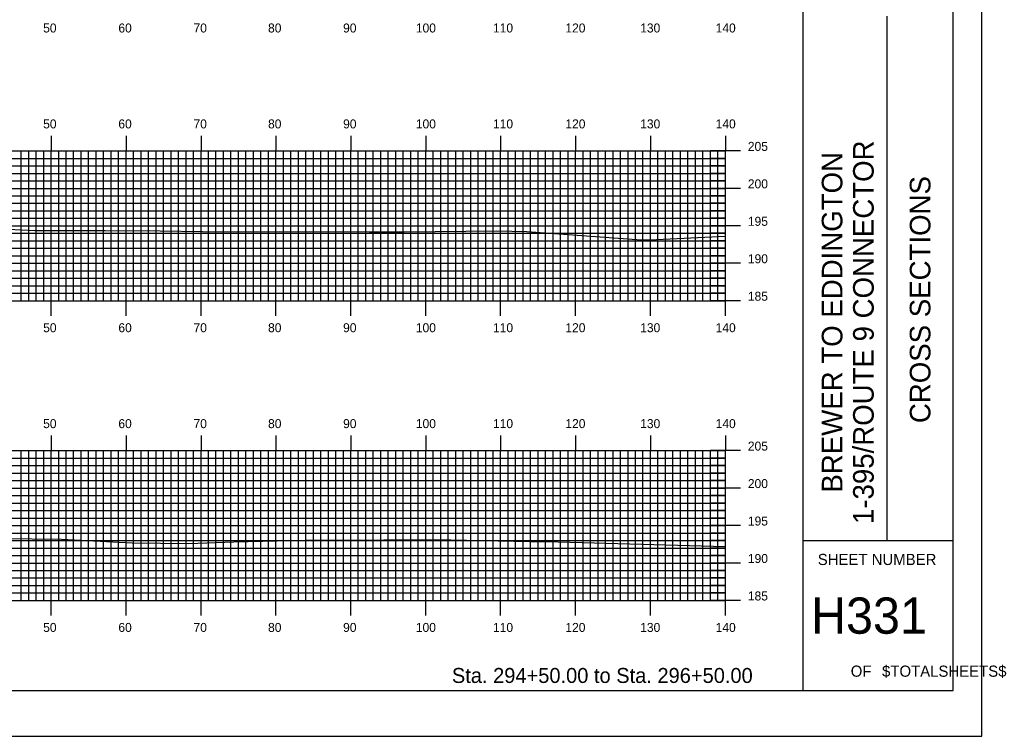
# Model space of a CAD drawing. Extents: x 1814522 to 1814865, y 442591 to 442811.
# Drawn here: x 1814733.3 to 1814865, y 442590.5 to 442686.2 of the extents above; entities that cross this region are included whole.
import ezdxf

# ---------------------------------------------------------------- set-up
doc = ezdxf.new("R2010")
doc.units = 0
for name, color, linetype in [('BORDER', 7, 'Continuous'), ('H_V ANNOTATION', 7, 'Continuous'), ('MAJOR', 7, 'Continuous'), ('MINOR', 7, 'Continuous'), ('PLOT BOUNDARY', 7, 'Continuous'), ('S_Roadway_Centerline', 7, 'Continuous')]:
    doc.layers.add(name, color=color, linetype=linetype)

msp = doc.modelspace()

# ---------------------------------------------------------------- linework, layer by layer
at = {"layer": 'BORDER'}
for p, q in [((1814837.91, 442596.67), (1814837.91, 442806.67)), ((1814849.09, 442616.67), (1814849.09, 442686.67)), ((1814837.91, 442616.67), (1814857.91, 442616.67))]:
    msp.add_line(p, q, dxfattribs=at)
msp.add_lwpolyline([(1814537.91, 442596.67), (1814857.91, 442596.67), (1814857.91, 442806.67), (1814537.91, 442806.67)], close=True, dxfattribs=at)
at = {"layer": 'MAJOR'}
for p, q in [((1814737.51, 442670.67), (1814737.51, 442668.67)), ((1814747.51, 442670.67), (1814747.51, 442668.67)), ((1814757.51, 442670.67), (1814757.51, 442668.67)), ((1814767.51, 442670.67), (1814767.51, 442668.67)), ((1814777.51, 442670.67), (1814777.51, 442668.67)), ((1814787.51, 442670.67), (1814787.51, 442668.67)), ((1814797.51, 442670.67), (1814797.51, 442668.67)), ((1814807.51, 442670.67), (1814807.51, 442668.67)), ((1814817.51, 442670.67), (1814817.51, 442668.67)), ((1814827.51, 442670.67), (1814827.51, 442668.67)), ((1814547.51, 442668.67), (1814827.51, 442668.67)), ((1814547.51, 442668.67), (1814827.51, 442668.67)), ((1814737.51, 442648.67), (1814737.51, 442668.67)), ((1814747.51, 442648.67), (1814747.51, 442668.67)), ((1814757.51, 442648.67), (1814757.51, 442668.67)), ((1814767.51, 442648.67), (1814767.51, 442668.67)), ((1814777.51, 442648.67), (1814777.51, 442668.67)), ((1814787.51, 442648.67), (1814787.51, 442668.67)), ((1814797.51, 442648.67), (1814797.51, 442668.67)), ((1814807.51, 442648.67), (1814807.51, 442668.67)), ((1814817.51, 442648.67), (1814817.51, 442668.67)), ((1814829.51, 442668.67), (1814825.5, 442668.67)), ((1814827.51, 442648.67), (1814827.51, 442668.67)), ((1814827.51, 442648.67), (1814827.51, 442668.67)), ((1814547.51, 442663.67), (1814827.51, 442663.67)), ((1814829.51, 442663.67), (1814825.5, 442663.67)), ((1814547.51, 442658.67), (1814827.51, 442658.67)), ((1814829.51, 442658.67), (1814825.5, 442658.67)), ((1814547.51, 442653.67), (1814827.51, 442653.67)), ((1814829.51, 442653.67), (1814825.5, 442653.67)), ((1814547.51, 442648.67), (1814827.51, 442648.67)), ((1814547.51, 442648.67), (1814827.51, 442648.67)), ((1814737.51, 442646.66), (1814737.51, 442648.67)), ((1814747.51, 442646.66), (1814747.51, 442648.67)), ((1814757.51, 442646.66), (1814757.51, 442648.67)), ((1814767.51, 442646.66), (1814767.51, 442648.67)), ((1814777.51, 442646.66), (1814777.51, 442648.67)), ((1814787.51, 442646.66), (1814787.51, 442648.67)), ((1814797.51, 442646.66), (1814797.51, 442648.67)), ((1814807.51, 442646.66), (1814807.51, 442648.67)), ((1814817.51, 442646.66), (1814817.51, 442648.67)), ((1814829.51, 442648.67), (1814825.5, 442648.67)), ((1814827.51, 442646.66), (1814827.51, 442648.67)), ((1814737.51, 442630.67), (1814737.51, 442628.67)), ((1814747.51, 442630.67), (1814747.51, 442628.67)), ((1814757.51, 442630.67), (1814757.51, 442628.67)), ((1814767.51, 442630.67), (1814767.51, 442628.67)), ((1814777.51, 442630.67), (1814777.51, 442628.67)), ((1814787.51, 442630.67), (1814787.51, 442628.67)), ((1814797.51, 442630.67), (1814797.51, 442628.67)), ((1814807.51, 442630.67), (1814807.51, 442628.67)), ((1814817.51, 442630.67), (1814817.51, 442628.67)), ((1814827.51, 442630.67), (1814827.51, 442628.67)), ((1814547.51, 442628.67), (1814827.51, 442628.67)), ((1814547.51, 442628.67), (1814827.51, 442628.67)), ((1814737.51, 442608.67), (1814737.51, 442628.67)), ((1814747.51, 442608.67), (1814747.51, 442628.67)), ((1814757.51, 442608.67), (1814757.51, 442628.67)), ((1814767.51, 442608.67), (1814767.51, 442628.67)), ((1814777.51, 442608.67), (1814777.51, 442628.67)), ((1814787.51, 442608.67), (1814787.51, 442628.67)), ((1814797.51, 442608.67), (1814797.51, 442628.67)), ((1814807.51, 442608.67), (1814807.51, 442628.67)), ((1814817.51, 442608.67), (1814817.51, 442628.67)), ((1814829.51, 442628.67), (1814825.5, 442628.67)), ((1814827.51, 442608.67), (1814827.51, 442628.67)), ((1814827.51, 442608.67), (1814827.51, 442628.67)), ((1814547.51, 442623.67), (1814827.51, 442623.67)), ((1814829.51, 442623.67), (1814825.5, 442623.67)), ((1814547.51, 442618.67), (1814827.51, 442618.67)), ((1814829.51, 442618.67), (1814825.5, 442618.67)), ((1814547.51, 442613.67), (1814827.51, 442613.67)), ((1814829.51, 442613.67), (1814825.5, 442613.67)), ((1814547.51, 442608.67), (1814827.51, 442608.67)), ((1814547.51, 442608.67), (1814827.51, 442608.67)), ((1814737.51, 442606.66), (1814737.51, 442608.67)), ((1814747.51, 442606.66), (1814747.51, 442608.67)), ((1814757.51, 442606.66), (1814757.51, 442608.67)), ((1814767.51, 442606.66), (1814767.51, 442608.67)), ((1814777.51, 442606.66), (1814777.51, 442608.67)), ((1814787.51, 442606.66), (1814787.51, 442608.67)), ((1814797.51, 442606.66), (1814797.51, 442608.67)), ((1814807.51, 442606.66), (1814807.51, 442608.67)), ((1814817.51, 442606.66), (1814817.51, 442608.67)), ((1814829.51, 442608.67), (1814825.5, 442608.67)), ((1814827.51, 442606.66), (1814827.51, 442608.67))]:
    msp.add_line(p, q, dxfattribs=at)
at = {"layer": 'MINOR'}
for p, q in [((1814733.51, 442648.67), (1814733.51, 442668.67)), ((1814734.51, 442648.67), (1814734.51, 442668.67)), ((1814735.51, 442648.67), (1814735.51, 442668.67)), ((1814736.51, 442648.67), (1814736.51, 442668.67)), ((1814738.51, 442648.67), (1814738.51, 442668.67)), ((1814739.51, 442648.67), (1814739.51, 442668.67)), ((1814740.51, 442648.67), (1814740.51, 442668.67)), ((1814741.51, 442648.67), (1814741.51, 442668.67)), ((1814742.51, 442648.67), (1814742.51, 442668.67)), ((1814743.51, 442648.67), (1814743.51, 442668.67)), ((1814744.51, 442648.67), (1814744.51, 442668.67)), ((1814745.51, 442648.67), (1814745.51, 442668.67)), ((1814746.51, 442648.67), (1814746.51, 442668.67)), ((1814748.51, 442648.67), (1814748.51, 442668.67)), ((1814749.51, 442648.67), (1814749.51, 442668.67)), ((1814750.51, 442648.67), (1814750.51, 442668.67)), ((1814751.51, 442648.67), (1814751.51, 442668.67)), ((1814752.51, 442648.67), (1814752.51, 442668.67)), ((1814753.51, 442648.67), (1814753.51, 442668.67)), ((1814754.51, 442648.67), (1814754.51, 442668.67)), ((1814755.51, 442648.67), (1814755.51, 442668.67)), ((1814756.51, 442648.67), (1814756.51, 442668.67)), ((1814758.51, 442648.67), (1814758.51, 442668.67)), ((1814759.51, 442648.67), (1814759.51, 442668.67)), ((1814760.51, 442648.67), (1814760.51, 442668.67)), ((1814761.51, 442648.67), (1814761.51, 442668.67)), ((1814762.51, 442648.67), (1814762.51, 442668.67)), ((1814763.51, 442648.67), (1814763.51, 442668.67)), ((1814764.51, 442648.67), (1814764.51, 442668.67)), ((1814765.51, 442648.67), (1814765.51, 442668.67)), ((1814766.51, 442648.67), (1814766.51, 442668.67)), ((1814768.51, 442648.67), (1814768.51, 442668.67)), ((1814769.51, 442648.67), (1814769.51, 442668.67)), ((1814770.51, 442648.67), (1814770.51, 442668.67)), ((1814771.51, 442648.67), (1814771.51, 442668.67)), ((1814772.51, 442648.67), (1814772.51, 442668.67)), ((1814773.51, 442648.67), (1814773.51, 442668.67)), ((1814774.51, 442648.67), (1814774.51, 442668.67)), ((1814775.51, 442648.67), (1814775.51, 442668.67)), ((1814776.51, 442648.67), (1814776.51, 442668.67)), ((1814778.51, 442648.67), (1814778.51, 442668.67)), ((1814779.51, 442648.67), (1814779.51, 442668.67)), ((1814780.51, 442648.67), (1814780.51, 442668.67)), ((1814781.51, 442648.67), (1814781.51, 442668.67)), ((1814782.51, 442648.67), (1814782.51, 442668.67)), ((1814783.51, 442648.67), (1814783.51, 442668.67)), ((1814784.51, 442648.67), (1814784.51, 442668.67)), ((1814785.51, 442648.67), (1814785.51, 442668.67)), ((1814786.51, 442648.67), (1814786.51, 442668.67)), ((1814788.51, 442648.67), (1814788.51, 442668.67)), ((1814789.51, 442648.67), (1814789.51, 442668.67)), ((1814790.51, 442648.67), (1814790.51, 442668.67)), ((1814791.51, 442648.67), (1814791.51, 442668.67)), ((1814792.51, 442648.67), (1814792.51, 442668.67)), ((1814793.51, 442648.67), (1814793.51, 442668.67)), ((1814794.51, 442648.67), (1814794.51, 442668.67)), ((1814795.51, 442648.67), (1814795.51, 442668.67)), ((1814796.51, 442648.67), (1814796.51, 442668.67)), ((1814798.51, 442648.67), (1814798.51, 442668.67)), ((1814799.51, 442648.67), (1814799.51, 442668.67)), ((1814800.51, 442648.67), (1814800.51, 442668.67)), ((1814801.51, 442648.67), (1814801.51, 442668.67)), ((1814802.51, 442648.67), (1814802.51, 442668.67)), ((1814803.51, 442648.67), (1814803.51, 442668.67)), ((1814804.51, 442648.67), (1814804.51, 442668.67)), ((1814805.51, 442648.67), (1814805.51, 442668.67)), ((1814806.51, 442648.67), (1814806.51, 442668.67)), ((1814808.51, 442648.67), (1814808.51, 442668.67)), ((1814809.51, 442648.67), (1814809.51, 442668.67)), ((1814810.51, 442648.67), (1814810.51, 442668.67)), ((1814811.51, 442648.67), (1814811.51, 442668.67)), ((1814812.51, 442648.67), (1814812.51, 442668.67)), ((1814813.51, 442648.67), (1814813.51, 442668.67)), ((1814814.51, 442648.67), (1814814.51, 442668.67)), ((1814815.51, 442648.67), (1814815.51, 442668.67)), ((1814816.51, 442648.67), (1814816.51, 442668.67)), ((1814818.51, 442648.67), (1814818.51, 442668.67)), ((1814819.51, 442648.67), (1814819.51, 442668.67)), ((1814820.51, 442648.67), (1814820.51, 442668.67)), ((1814821.51, 442648.67), (1814821.51, 442668.67)), ((1814822.51, 442648.67), (1814822.51, 442668.67)), ((1814823.51, 442648.67), (1814823.51, 442668.67)), ((1814824.51, 442648.67), (1814824.51, 442668.67)), ((1814825.51, 442648.67), (1814825.51, 442668.67)), ((1814826.51, 442648.67), (1814826.51, 442668.67)), ((1814547.51, 442667.67), (1814827.51, 442667.67)), ((1814547.51, 442666.67), (1814827.51, 442666.67)), ((1814827.51, 442667.67), (1814825.5, 442667.67)), ((1814827.51, 442666.67), (1814825.5, 442666.67)), ((1814547.51, 442665.67), (1814827.51, 442665.67)), ((1814827.51, 442665.67), (1814825.5, 442665.67)), ((1814547.51, 442664.67), (1814827.51, 442664.67)), ((1814827.51, 442664.67), (1814825.5, 442664.67)), ((1814547.51, 442662.67), (1814827.51, 442662.67)), ((1814827.51, 442662.67), (1814825.5, 442662.67)), ((1814547.51, 442661.67), (1814827.51, 442661.67)), ((1814827.51, 442661.67), (1814825.5, 442661.67)), ((1814547.51, 442660.67), (1814827.51, 442660.67)), ((1814827.51, 442660.67), (1814825.5, 442660.67)), ((1814547.51, 442659.67), (1814827.51, 442659.67)), ((1814827.51, 442659.67), (1814825.5, 442659.67)), ((1814547.51, 442657.67), (1814827.51, 442657.67)), ((1814827.51, 442657.67), (1814825.5, 442657.67)), ((1814547.51, 442656.67), (1814827.51, 442656.67)), ((1814827.51, 442656.67), (1814825.5, 442656.67)), ((1814547.51, 442655.67), (1814827.51, 442655.67)), ((1814547.51, 442654.67), (1814827.51, 442654.67)), ((1814827.51, 442655.67), (1814825.5, 442655.67)), ((1814827.51, 442654.67), (1814825.5, 442654.67)), ((1814547.51, 442652.67), (1814827.51, 442652.67)), ((1814827.51, 442652.67), (1814825.5, 442652.67)), ((1814547.51, 442651.67), (1814827.51, 442651.67)), ((1814547.51, 442650.67), (1814827.51, 442650.67)), ((1814827.51, 442651.67), (1814825.5, 442651.67)), ((1814827.51, 442650.67), (1814825.5, 442650.67)), ((1814547.51, 442649.67), (1814827.51, 442649.67)), ((1814827.51, 442649.67), (1814825.5, 442649.67)), ((1814733.51, 442608.67), (1814733.51, 442628.67)), ((1814734.51, 442608.67), (1814734.51, 442628.67)), ((1814735.51, 442608.67), (1814735.51, 442628.67)), ((1814736.51, 442608.67), (1814736.51, 442628.67)), ((1814738.51, 442608.67), (1814738.51, 442628.67)), ((1814739.51, 442608.67), (1814739.51, 442628.67)), ((1814740.51, 442608.67), (1814740.51, 442628.67)), ((1814741.51, 442608.67), (1814741.51, 442628.67)), ((1814742.51, 442608.67), (1814742.51, 442628.67)), ((1814743.51, 442608.67), (1814743.51, 442628.67)), ((1814744.51, 442608.67), (1814744.51, 442628.67)), ((1814745.51, 442608.67), (1814745.51, 442628.67)), ((1814746.51, 442608.67), (1814746.51, 442628.67)), ((1814748.51, 442608.67), (1814748.51, 442628.67)), ((1814749.51, 442608.67), (1814749.51, 442628.67)), ((1814750.51, 442608.67), (1814750.51, 442628.67)), ((1814751.51, 442608.67), (1814751.51, 442628.67)), ((1814752.51, 442608.67), (1814752.51, 442628.67)), ((1814753.51, 442608.67), (1814753.51, 442628.67)), ((1814754.51, 442608.67), (1814754.51, 442628.67)), ((1814755.51, 442608.67), (1814755.51, 442628.67)), ((1814756.51, 442608.67), (1814756.51, 442628.67)), ((1814758.51, 442608.67), (1814758.51, 442628.67)), ((1814759.51, 442608.67), (1814759.51, 442628.67)), ((1814760.51, 442608.67), (1814760.51, 442628.67)), ((1814761.51, 442608.67), (1814761.51, 442628.67)), ((1814762.51, 442608.67), (1814762.51, 442628.67)), ((1814763.51, 442608.67), (1814763.51, 442628.67)), ((1814764.51, 442608.67), (1814764.51, 442628.67)), ((1814765.51, 442608.67), (1814765.51, 442628.67)), ((1814766.51, 442608.67), (1814766.51, 442628.67)), ((1814768.51, 442608.67), (1814768.51, 442628.67)), ((1814769.51, 442608.67), (1814769.51, 442628.67)), ((1814770.51, 442608.67), (1814770.51, 442628.67)), ((1814771.51, 442608.67), (1814771.51, 442628.67)), ((1814772.51, 442608.67), (1814772.51, 442628.67)), ((1814773.51, 442608.67), (1814773.51, 442628.67)), ((1814774.51, 442608.67), (1814774.51, 442628.67)), ((1814775.51, 442608.67), (1814775.51, 442628.67)), ((1814776.51, 442608.67), (1814776.51, 442628.67)), ((1814778.51, 442608.67), (1814778.51, 442628.67)), ((1814779.51, 442608.67), (1814779.51, 442628.67)), ((1814780.51, 442608.67), (1814780.51, 442628.67)), ((1814781.51, 442608.67), (1814781.51, 442628.67)), ((1814782.51, 442608.67), (1814782.51, 442628.67)), ((1814783.51, 442608.67), (1814783.51, 442628.67)), ((1814784.51, 442608.67), (1814784.51, 442628.67)), ((1814785.51, 442608.67), (1814785.51, 442628.67)), ((1814786.51, 442608.67), (1814786.51, 442628.67)), ((1814788.51, 442608.67), (1814788.51, 442628.67)), ((1814789.51, 442608.67), (1814789.51, 442628.67)), ((1814790.51, 442608.67), (1814790.51, 442628.67)), ((1814791.51, 442608.67), (1814791.51, 442628.67)), ((1814792.51, 442608.67), (1814792.51, 442628.67)), ((1814793.51, 442608.67), (1814793.51, 442628.67)), ((1814794.51, 442608.67), (1814794.51, 442628.67)), ((1814795.51, 442608.67), (1814795.51, 442628.67)), ((1814796.51, 442608.67), (1814796.51, 442628.67)), ((1814798.51, 442608.67), (1814798.51, 442628.67)), ((1814799.51, 442608.67), (1814799.51, 442628.67)), ((1814800.51, 442608.67), (1814800.51, 442628.67)), ((1814801.51, 442608.67), (1814801.51, 442628.67)), ((1814802.51, 442608.67), (1814802.51, 442628.67)), ((1814803.51, 442608.67), (1814803.51, 442628.67)), ((1814804.51, 442608.67), (1814804.51, 442628.67)), ((1814805.51, 442608.67), (1814805.51, 442628.67)), ((1814806.51, 442608.67), (1814806.51, 442628.67)), ((1814808.51, 442608.67), (1814808.51, 442628.67)), ((1814809.51, 442608.67), (1814809.51, 442628.67)), ((1814810.51, 442608.67), (1814810.51, 442628.67)), ((1814811.51, 442608.67), (1814811.51, 442628.67)), ((1814812.51, 442608.67), (1814812.51, 442628.67)), ((1814813.51, 442608.67), (1814813.51, 442628.67)), ((1814814.51, 442608.67), (1814814.51, 442628.67)), ((1814815.51, 442608.67), (1814815.51, 442628.67)), ((1814816.51, 442608.67), (1814816.51, 442628.67)), ((1814818.51, 442608.67), (1814818.51, 442628.67)), ((1814819.51, 442608.67), (1814819.51, 442628.67)), ((1814820.51, 442608.67), (1814820.51, 442628.67)), ((1814821.51, 442608.67), (1814821.51, 442628.67)), ((1814822.51, 442608.67), (1814822.51, 442628.67)), ((1814823.51, 442608.67), (1814823.51, 442628.67)), ((1814824.51, 442608.67), (1814824.51, 442628.67)), ((1814825.51, 442608.67), (1814825.51, 442628.67)), ((1814826.51, 442608.67), (1814826.51, 442628.67)), ((1814547.51, 442627.67), (1814827.51, 442627.67)), ((1814827.51, 442627.67), (1814825.5, 442627.67)), ((1814547.51, 442626.67), (1814827.51, 442626.67)), ((1814547.51, 442625.67), (1814827.51, 442625.67)), ((1814827.51, 442626.67), (1814825.5, 442626.67)), ((1814827.51, 442625.67), (1814825.5, 442625.67)), ((1814547.51, 442624.67), (1814827.51, 442624.67)), ((1814827.51, 442624.67), (1814825.5, 442624.67)), ((1814547.51, 442622.67), (1814827.51, 442622.67)), ((1814547.51, 442621.67), (1814827.51, 442621.67)), ((1814827.51, 442622.67), (1814825.5, 442622.67)), ((1814827.51, 442621.67), (1814825.5, 442621.67)), ((1814547.51, 442620.67), (1814827.51, 442620.67)), ((1814827.51, 442620.67), (1814825.5, 442620.67)), ((1814547.51, 442619.67), (1814827.51, 442619.67)), ((1814827.51, 442619.67), (1814825.5, 442619.67)), ((1814547.51, 442617.67), (1814827.51, 442617.67)), ((1814827.51, 442617.67), (1814825.5, 442617.67)), ((1814547.51, 442616.67), (1814827.51, 442616.67)), ((1814827.51, 442616.67), (1814825.5, 442616.67)), ((1814547.51, 442615.67), (1814827.51, 442615.67)), ((1814827.51, 442615.67), (1814825.5, 442615.67)), ((1814547.51, 442614.67), (1814827.51, 442614.67)), ((1814827.51, 442614.67), (1814825.5, 442614.67)), ((1814547.51, 442612.67), (1814827.51, 442612.67)), ((1814827.51, 442612.67), (1814825.5, 442612.67)), ((1814547.51, 442611.67), (1814827.51, 442611.67)), ((1814827.51, 442611.67), (1814825.5, 442611.67)), ((1814547.51, 442610.67), (1814827.51, 442610.67)), ((1814827.51, 442610.67), (1814825.5, 442610.67)), ((1814547.51, 442609.67), (1814827.51, 442609.67)), ((1814827.51, 442609.67), (1814825.5, 442609.67))]:
    msp.add_line(p, q, dxfattribs=at)
at = {"layer": 'PLOT BOUNDARY'}
msp.add_lwpolyline([(1814521.72, 442590.55), (1814861.72, 442590.55), (1814861.72, 442810.55), (1814521.72, 442810.55)], close=True, dxfattribs=at)
at = {"layer": 'S_Roadway_Centerline'}
for points in [[(1814727.24, 442658.44), (1814735.31, 442658.05), (1814744.73, 442658.05), (1814752.08, 442658.01), (1814757.69, 442657.89), (1814780, 442657.86), (1814784.65, 442657.87), (1814797.01, 442657.99), (1814800.99, 442657.9), (1814815.67, 442656.86), (1814817.37, 442656.82), (1814827.51, 442657.3)], [(1814730.99, 442616.95), (1814738.9, 442616.86), (1814748.3, 442616.35), (1814755.89, 442616.28), (1814761.91, 442616.5), (1814771.56, 442616.71), (1814781.91, 442616.78), (1814788.77, 442616.79), (1814801.38, 442616.54), (1814805.18, 442616.48), (1814827.51, 442615.89)]]:
    msp.add_lwpolyline(points, dxfattribs=at)

# ---------------------------------------------------------------- texts
at = {"layer": 'BORDER'}
for s, p in [('1-395/ROUTE 9 CONNECTOR', (1814847.31, 442618.87)), ('BREWER TO EDDINGTON', (1814843.13, 442623.07)), ('CROSS SECTIONS', (1814854.88, 442632.34))]:
    msp.add_text(s, height=2.7557, rotation=90, dxfattribs=at).set_placement(p)
for s, height, p in [('SHEET NUMBER', 1.4905, (1814839.84, 442613.4)), ('H331', 4.839, (1814838.94, 442604.23)), ('OF', 1.491, (1814844.24, 442598.49)), ('$TOTALSHEETS$', 1.4905, (1814848.42, 442598.49))]:
    msp.add_text(s, height=height, dxfattribs=at).set_placement(p)
at = {"layer": 'H_V ANNOTATION'}
for s, height, p in [('50', 1.2, (1814736.44, 442684.47)), ('60', 1.2, (1814746.48, 442684.47)), ('70', 1.2, (1814756.51, 442684.47)), ('80', 1.2, (1814766.46, 442684.47)), ('90', 1.2, (1814776.48, 442684.47)), ('100', 1.2, (1814786.19, 442684.47)), ('110', 1.2, (1814796.49, 442684.47)), ('120', 1.2, (1814806.15, 442684.47)), ('130', 1.2, (1814816.14, 442684.47)), ('140', 1.2, (1814826.21, 442684.47)), ('50', 1.2, (1814736.44, 442671.67)), ('60', 1.2, (1814746.48, 442671.67)), ('70', 1.2, (1814756.51, 442671.67)), ('80', 1.2, (1814766.46, 442671.67)), ('90', 1.2, (1814776.48, 442671.67)), ('100', 1.2, (1814786.19, 442671.67)), ('110', 1.2, (1814796.49, 442671.67)), ('120', 1.2, (1814806.15, 442671.67)), ('130', 1.2, (1814816.14, 442671.67)), ('140', 1.2, (1814826.21, 442671.67)), ('205', 1.2, (1814830.51, 442668.67)), ('200', 1.2, (1814830.51, 442663.67)), ('195', 1.2, (1814830.51, 442658.67)), ('190', 1.2, (1814830.51, 442653.67)), ('185', 1.2, (1814830.51, 442648.67)), ('50', 1.2, (1814736.44, 442644.47)), ('60', 1.2, (1814746.48, 442644.47)), ('70', 1.2, (1814756.51, 442644.47)), ('80', 1.2, (1814766.46, 442644.47)), ('90', 1.2, (1814776.48, 442644.47)), ('100', 1.2, (1814786.19, 442644.47)), ('110', 1.2, (1814796.49, 442644.47)), ('120', 1.2, (1814806.15, 442644.47)), ('130', 1.2, (1814816.14, 442644.47)), ('140', 1.2, (1814826.21, 442644.47)), ('50', 1.2, (1814736.44, 442631.67)), ('60', 1.2, (1814746.48, 442631.67)), ('70', 1.2, (1814756.51, 442631.67)), ('80', 1.2, (1814766.46, 442631.67)), ('90', 1.2, (1814776.48, 442631.67)), ('100', 1.2, (1814786.19, 442631.67)), ('110', 1.2, (1814796.49, 442631.67)), ('120', 1.2, (1814806.15, 442631.67)), ('130', 1.2, (1814816.14, 442631.67)), ('140', 1.2, (1814826.21, 442631.67)), ('205', 1.2, (1814830.51, 442628.67)), ('200', 1.2, (1814830.51, 442623.67)), ('195', 1.2, (1814830.51, 442618.67)), ('190', 1.2, (1814830.51, 442613.67)), ('185', 1.2, (1814830.51, 442608.67)), ('50', 1.2, (1814736.44, 442604.47)), ('60', 1.2, (1814746.48, 442604.47)), ('70', 1.2, (1814756.51, 442604.47)), ('80', 1.2, (1814766.46, 442604.47)), ('90', 1.2, (1814776.48, 442604.47)), ('100', 1.2, (1814786.19, 442604.47)), ('110', 1.2, (1814796.49, 442604.47)), ('120', 1.2, (1814806.15, 442604.47)), ('130', 1.2, (1814816.14, 442604.47)), ('140', 1.2, (1814826.21, 442604.47)), ('Sta. 294+50.00 to Sta. 296+50.00', 2.0004, (1814791, 442597.66))]:
    msp.add_text(s, height=height, dxfattribs=at).set_placement(p)

doc.saveas('drawing.dxf')
